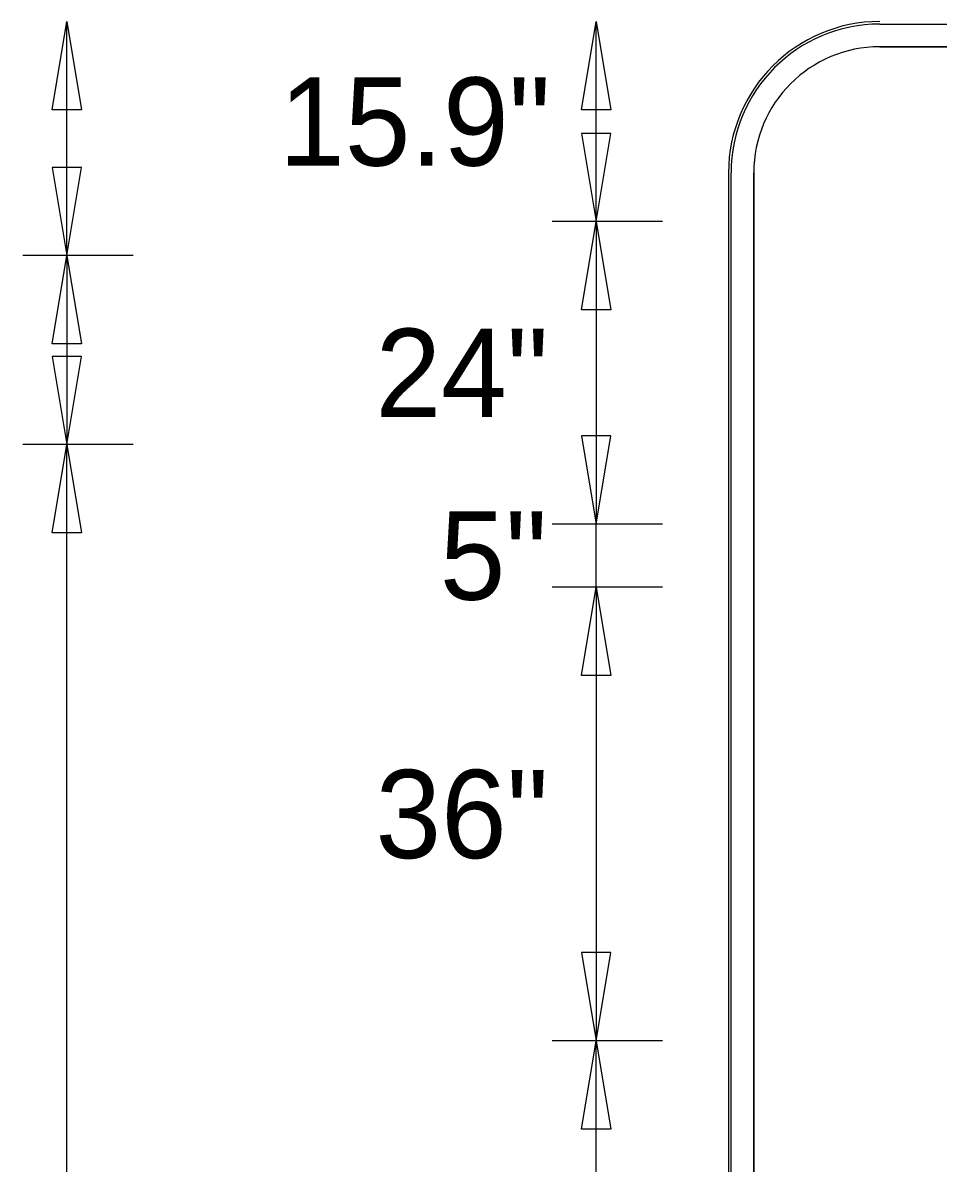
# Model space of a CAD drawing. Extents: x 2149934 to 2150188, y 145114 to 145238.
# Drawn here: x 2150026.85 to 2150032.91, y 145149.83 to 145157.37 of the extents above; entities that cross this region are included whole.
import ezdxf

# ---------------------------------------------------------------- set-up
doc = ezdxf.new("R2010")
doc.units = 0
for name, color, linetype in [('GSBWFILL', 7, 'Continuous'), ('GSCOLORFILL', 7, 'Continuous'), ('GSDIMS', 7, 'Continuous'), ('GSOUTLINE', 7, 'Continuous')]:
    doc.layers.add(name, color=color, linetype=linetype)

msp = doc.modelspace()

# ---------------------------------------------------------------- linework, layer by layer
at = {"layer": 'GSBWFILL'}
for p, q in [((2150032.5199, 145157.216), (2150046.0199, 145157.216)), ((2150031.5199, 145156.3826), (2150031.5199, 145145.3826)), ((2150031.6865, 145145.3826), (2150031.6865, 145156.3826))]:
    msp.add_line(p, q, dxfattribs=at)
for radius in [1, 0.8333]:
    msp.add_arc((2150032.5199, 145156.3826), radius, 90, 180, dxfattribs=at)
at = {"layer": 'GSCOLORFILL'}
for p, q in [((2150032.5199, 145157.366), (2150046.0199, 145157.366)), ((2150032.5199, 145157.216), (2150046.0199, 145157.216)), ((2150031.5199, 145156.3826), (2150031.5199, 145145.3826)), ((2150031.5199, 145156.3826), (2150031.5199, 145145.3826)), ((2150031.5199, 145156.3826), (2150031.5199, 145145.3826)), ((2150031.5365, 145145.3826), (2150031.5365, 145156.3826)), ((2150031.6865, 145145.3826), (2150031.6865, 145156.3826))]:
    msp.add_line(p, q, dxfattribs=at)
for radius in [1, 1, 1, 0.9833, 0.8333]:
    msp.add_arc((2150032.5199, 145156.3826), radius, 90, 180, dxfattribs=at)
at = {"layer": 'GSDIMS'}
for p, q in [((2150027.1448, 145155.8352), (2150027.1448, 145157.3827)), ((2150030.6448, 145156.0601), (2150030.6448, 145157.3827)), ((2150031.0823, 145156.0601), (2150030.3531, 145156.0601)), ((2150031.0823, 145156.0601), (2150030.3531, 145156.0601)), ((2150030.6448, 145156.0601), (2150030.6448, 145154.06)), ((2150027.5823, 145155.8352), (2150026.8531, 145155.8352)), ((2150027.5823, 145155.8352), (2150026.8531, 145155.8352)), ((2150027.1448, 145155.8352), (2150027.1448, 145154.5852)), ((2150027.5823, 145154.5852), (2150026.8531, 145154.5852)), ((2150027.5823, 145154.5852), (2150026.8531, 145154.5852)), ((2150027.1448, 145144.3826), (2150027.1448, 145154.5852)), ((2150031.0823, 145154.06), (2150030.3531, 145154.06)), ((2150031.0823, 145154.06), (2150030.3531, 145154.06)), ((2150030.6448, 145153.6434), (2150030.6448, 145154.06)), ((2150031.0823, 145153.6434), (2150030.3531, 145153.6434)), ((2150031.0823, 145153.6434), (2150030.3531, 145153.6434)), ((2150030.6448, 145153.6434), (2150030.6448, 145150.6434)), ((2150031.0823, 145150.6434), (2150030.3531, 145150.6434)), ((2150031.0823, 145150.6434), (2150030.3531, 145150.6434)), ((2150030.6448, 145147.2435), (2150030.6448, 145150.6434))]:
    msp.add_line(p, q, dxfattribs=at)
for points in [[(2150027.1448, 145157.3827), (2150027.242, 145156.7994), (2150027.0476, 145156.7994)], [(2150030.6448, 145157.3827), (2150030.742, 145156.7994), (2150030.5476, 145156.7994)], [(2150030.6448, 145156.0601), (2150030.742, 145156.6434), (2150030.5476, 145156.6434)], [(2150027.1448, 145155.8352), (2150027.242, 145156.4186), (2150027.0476, 145156.4186)], [(2150030.6448, 145156.0601), (2150030.742, 145155.4768), (2150030.5476, 145155.4768)], [(2150027.1448, 145155.8352), (2150027.242, 145155.2519), (2150027.0476, 145155.2519)], [(2150027.1448, 145154.5852), (2150027.242, 145155.1686), (2150027.0476, 145155.1686)], [(2150030.6448, 145154.06), (2150030.742, 145154.6433), (2150030.5476, 145154.6433)], [(2150027.1448, 145154.5852), (2150027.242, 145154.0019), (2150027.0476, 145154.0019)], [(2150030.6448, 145153.6434), (2150030.742, 145153.0601), (2150030.5476, 145153.0601)], [(2150030.6448, 145150.6434), (2150030.742, 145151.2267), (2150030.5476, 145151.2267)], [(2150030.6448, 145150.6434), (2150030.742, 145150.0601), (2150030.5476, 145150.0601)]]:
    msp.add_lwpolyline(points, close=True, dxfattribs=at)
at = {"layer": 'GSOUTLINE'}
for p, q in [((2150046.0199, 145157.216), (2150032.5199, 145157.216)), ((2150031.5199, 145156.3826), (2150031.5199, 145145.3826)), ((2150031.6865, 145156.3826), (2150031.6865, 145145.3826))]:
    msp.add_line(p, q, dxfattribs=at)
for radius in [1, 0.8333]:
    msp.add_arc((2150032.5199, 145156.3826), radius, 90, 180, dxfattribs=at)

# ---------------------------------------------------------------- texts
at = {"layer": 'GSDIMS'}
for s, p in [('15.9"', (2150028.5484, 145156.4297)), ('24"', (2150029.1854, 145154.7684)), ('5"', (2150029.6101, 145153.56)), ('36"', (2150029.1854, 145151.8517))]:
    msp.add_text(s, height=0.58333, dxfattribs=at).set_placement(p)

doc.saveas('drawing.dxf')
